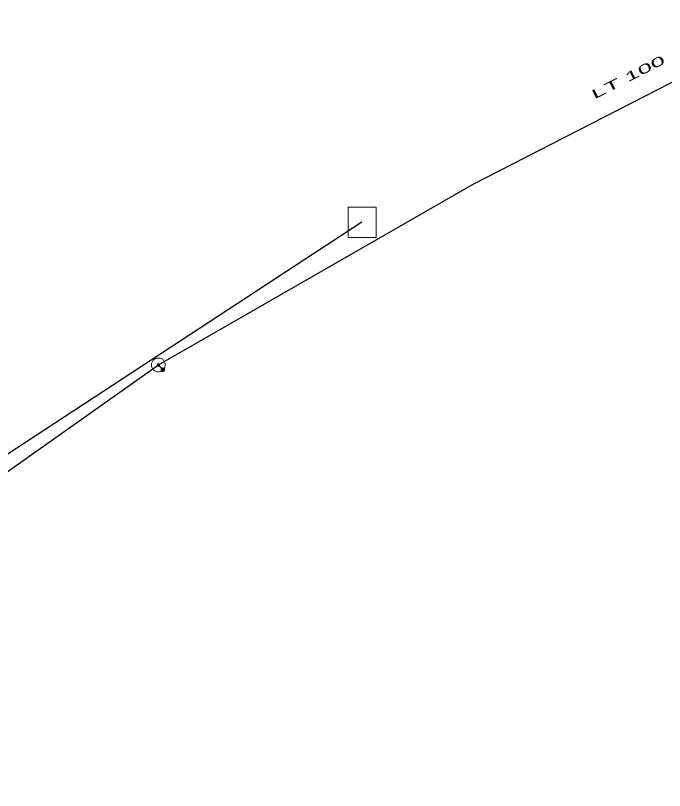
# Model space of a CAD drawing. Extents: x -688296 to -687852, y -973332 to -972816.
# Drawn here: x -687982.8 to -687935.8, y -973181.4 to -973125.3 of the extents above; entities that cross this region are included whole.
import ezdxf
from ezdxf.enums import TextEntityAlignment as Align

# ---------------------------------------------------------------- set-up
doc = ezdxf.new("R2010")
doc.units = 0
doc.header["$LTSCALE"] = 0.27
for name, color, linetype, lineweight in [('1', 7, 'Continuous', 25), ('14', 7, 'Continuous', 13), ('17', 7, 'Continuous', 25), ('22', 7, 'Continuous', 13), ('47', 7, 'Continuous', 13), ('9', 7, 'Continuous', 13)]:
    doc.layers.add(name, color=color, linetype=linetype, lineweight=lineweight)

msp = doc.modelspace()

# ---------------------------------------------------------------- linework, layer by layer
at = {"layer": '14', "lineweight": 25}
msp.add_line((-687957.712, -973140.243), (-688017.39, -973179.289), dxfattribs=at)
at = {"layer": '14'}
msp.add_line((-687972.436, -973150.573), (-687972.119, -973150.919), dxfattribs=at)
at = {"layer": '17'}
for points in [[(-687972.436, -973150.573), (-687949.647, -973137.493), (-687925.819, -973125.269)], [(-687987.568, -973219.849), (-688011, -973191.963), (-688018.429, -973183.079), (-687972.436, -973150.573)]]:
    msp.add_lwpolyline(points, dxfattribs=at)
at = {"layer": '22'}
msp.add_lwpolyline([(-687958.692, -973139.153), (-687956.659, -973139.153), (-687956.659, -973141.346), (-687958.692, -973141.346)], close=True, dxfattribs=at)
at = {"layer": '47'}
for points in [[(-687972.098, -973150.941), (-687972.061, -973150.904), (-687972.028, -973150.863), (-687972.001, -973150.819), (-687971.977, -973150.772), (-687971.959, -973150.723), (-687971.946, -973150.672), (-687971.939, -973150.62), (-687971.936, -973150.568), (-687971.939, -973150.516), (-687971.947, -973150.464), (-687971.961, -973150.413), (-687971.981, -973150.365), (-687972.005, -973150.319), (-687972.034, -973150.275), (-687972.067, -973150.235), (-687972.104, -973150.198), (-687972.145, -973150.165), (-687972.19, -973150.137), (-687972.236, -973150.114), (-687972.285, -973150.096), (-687972.336, -973150.083), (-687972.388, -973150.075), (-687972.441, -973150.073), (-687972.492, -973150.075), (-687972.544, -973150.084), (-687972.595, -973150.098), (-687972.644, -973150.117), (-687972.689, -973150.142), (-687972.733, -973150.171), (-687972.773, -973150.204), (-687972.81, -973150.241), (-687972.843, -973150.282), (-687972.871, -973150.326), (-687972.894, -973150.373), (-687972.912, -973150.422), (-687972.926, -973150.472), (-687972.934, -973150.525), (-687972.936, -973150.577), (-687972.933, -973150.629), (-687972.924, -973150.681), (-687972.91, -973150.732), (-687972.891, -973150.78), (-687972.866, -973150.826), (-687972.837, -973150.87), (-687972.804, -973150.91), (-687972.767, -973150.947), (-687972.726, -973150.98), (-687972.682, -973151.008), (-687972.635, -973151.031), (-687972.586, -973151.049), (-687972.536, -973151.063), (-687972.484, -973151.07), (-687972.432, -973151.072), (-687972.379, -973151.069), (-687972.327, -973151.061), (-687972.276, -973151.047), (-687972.229, -973151.027), (-687972.182, -973151.003), (-687972.138, -973150.974)], [(-687972.38, -973150.633), (-687972.373, -973150.627), (-687972.369, -973150.62), (-687972.364, -973150.613), (-687972.361, -973150.606), (-687972.357, -973150.597), (-687972.356, -973150.589), (-687972.354, -973150.58), (-687972.353, -973150.572), (-687972.354, -973150.563), (-687972.355, -973150.555), (-687972.358, -973150.546), (-687972.361, -973150.538), (-687972.365, -973150.531), (-687972.369, -973150.524), (-687972.375, -973150.517), (-687972.381, -973150.51), (-687972.388, -973150.506), (-687972.395, -973150.501), (-687972.402, -973150.498), (-687972.411, -973150.494), (-687972.419, -973150.493), (-687972.428, -973150.491), (-687972.436, -973150.49), (-687972.445, -973150.491), (-687972.453, -973150.492), (-687972.462, -973150.495), (-687972.47, -973150.498), (-687972.477, -973150.502), (-687972.484, -973150.506), (-687972.491, -973150.512), (-687972.498, -973150.518), (-687972.502, -973150.525), (-687972.507, -973150.532), (-687972.51, -973150.539), (-687972.514, -973150.548), (-687972.516, -973150.556), (-687972.517, -973150.565), (-687972.518, -973150.573), (-687972.517, -973150.582), (-687972.516, -973150.59), (-687972.513, -973150.599), (-687972.51, -973150.607), (-687972.506, -973150.614), (-687972.502, -973150.621), (-687972.496, -973150.628), (-687972.49, -973150.635), (-687972.483, -973150.639), (-687972.476, -973150.644), (-687972.469, -973150.647), (-687972.46, -973150.651), (-687972.452, -973150.653), (-687972.443, -973150.654), (-687972.435, -973150.655), (-687972.426, -973150.654), (-687972.418, -973150.653), (-687972.409, -973150.65), (-687972.401, -973150.647), (-687972.394, -973150.643), (-687972.387, -973150.639)]]:
    msp.add_lwpolyline(points, close=True, dxfattribs=at)
at = {"layer": '9'}
for points in [[(-687972.245, -973150.919), (-687972.245, -973150.932), (-687972.242, -973150.945), (-687972.24, -973150.958), (-687972.235, -973150.97), (-687972.228, -973150.982), (-687972.222, -973150.993), (-687972.213, -973151.003), (-687972.203, -973151.013), (-687972.193, -973151.021), (-687972.183, -973151.028), (-687972.171, -973151.034), (-687972.159, -973151.039), (-687972.146, -973151.042), (-687972.132, -973151.044), (-687972.12, -973151.046), (-687972.107, -973151.045), (-687972.093, -973151.043), (-687972.081, -973151.04), (-687972.068, -973151.035), (-687972.056, -973151.029), (-687972.046, -973151.022), (-687972.036, -973151.014), (-687972.026, -973151.004), (-687972.017, -973150.994), (-687972.011, -973150.983), (-687972.005, -973150.971), (-687972, -973150.959), (-687971.997, -973150.946), (-687971.995, -973150.933), (-687971.992, -973150.92), (-687971.994, -973150.907), (-687971.995, -973150.894), (-687971.999, -973150.881), (-687972.004, -973150.869), (-687972.009, -973150.857), (-687972.017, -973150.846), (-687972.024, -973150.836), (-687972.034, -973150.826), (-687972.044, -973150.818), (-687972.056, -973150.811), (-687972.068, -973150.805), (-687972.08, -973150.8), (-687972.093, -973150.797), (-687972.105, -973150.795), (-687972.119, -973150.794), (-687972.132, -973150.794), (-687972.144, -973150.796), (-687972.157, -973150.799), (-687972.169, -973150.804), (-687972.181, -973150.81), (-687972.193, -973150.817), (-687972.203, -973150.825), (-687972.213, -973150.835), (-687972.22, -973150.845), (-687972.228, -973150.856), (-687972.233, -973150.868), (-687972.239, -973150.88), (-687972.242, -973150.893), (-687972.244, -973150.906)], [(-687972.225, -973150.919), (-687972.225, -973150.93), (-687972.223, -973150.941), (-687972.22, -973150.952), (-687972.217, -973150.962), (-687972.212, -973150.972), (-687972.206, -973150.981), (-687972.198, -973150.99), (-687972.191, -973150.998), (-687972.181, -973151.005), (-687972.173, -973151.011), (-687972.163, -973151.016), (-687972.152, -973151.02), (-687972.142, -973151.023), (-687972.13, -973151.026), (-687972.12, -973151.026), (-687972.108, -973151.026), (-687972.098, -973151.024), (-687972.087, -973151.021), (-687972.076, -973151.017), (-687972.066, -973151.012), (-687972.058, -973151.006), (-687972.049, -973150.999), (-687972.041, -973150.991), (-687972.034, -973150.982), (-687972.027, -973150.973), (-687972.022, -973150.963), (-687972.019, -973150.953), (-687972.016, -973150.942), (-687972.014, -973150.931), (-687972.012, -973150.92), (-687972.012, -973150.909), (-687972.014, -973150.898), (-687972.017, -973150.887), (-687972.022, -973150.877), (-687972.027, -973150.867), (-687972.032, -973150.858), (-687972.039, -973150.849), (-687972.048, -973150.841), (-687972.056, -973150.834), (-687972.066, -973150.828), (-687972.076, -973150.823), (-687972.085, -973150.819), (-687972.097, -973150.816), (-687972.107, -973150.814), (-687972.119, -973150.814), (-687972.13, -973150.813), (-687972.141, -973150.815), (-687972.152, -973150.818), (-687972.161, -973150.822), (-687972.171, -973150.827), (-687972.181, -973150.833), (-687972.19, -973150.84), (-687972.198, -973150.848), (-687972.205, -973150.857), (-687972.21, -973150.866), (-687972.215, -973150.876), (-687972.22, -973150.886), (-687972.223, -973150.897), (-687972.225, -973150.908)], [(-687972.206, -973150.919), (-687972.206, -973150.928), (-687972.205, -973150.937), (-687972.201, -973150.946), (-687972.198, -973150.954), (-687972.195, -973150.962), (-687972.19, -973150.97), (-687972.183, -973150.977), (-687972.178, -973150.983), (-687972.171, -973150.989), (-687972.163, -973150.994), (-687972.154, -973150.998), (-687972.147, -973151.001), (-687972.137, -973151.004), (-687972.129, -973151.005), (-687972.12, -973151.007), (-687972.11, -973151.006), (-687972.102, -973151.005), (-687972.093, -973151.002), (-687972.085, -973150.999), (-687972.076, -973150.995), (-687972.068, -973150.99), (-687972.061, -973150.984), (-687972.056, -973150.978), (-687972.049, -973150.971), (-687972.044, -973150.963), (-687972.041, -973150.955), (-687972.038, -973150.947), (-687972.034, -973150.938), (-687972.034, -973150.929), (-687972.031, -973150.92), (-687972.032, -973150.911), (-687972.034, -973150.902), (-687972.036, -973150.893), (-687972.039, -973150.885), (-687972.044, -973150.877), (-687972.049, -973150.869), (-687972.054, -973150.862), (-687972.061, -973150.856), (-687972.068, -973150.85), (-687972.076, -973150.845), (-687972.083, -973150.841), (-687972.092, -973150.838), (-687972.1, -973150.835), (-687972.11, -973150.834), (-687972.119, -973150.833), (-687972.127, -973150.833), (-687972.137, -973150.834), (-687972.146, -973150.837), (-687972.154, -973150.84), (-687972.161, -973150.844), (-687972.169, -973150.849), (-687972.176, -973150.855), (-687972.183, -973150.861), (-687972.188, -973150.868), (-687972.193, -973150.876), (-687972.198, -973150.884), (-687972.201, -973150.892), (-687972.203, -973150.901), (-687972.205, -973150.91)], [(-687972.186, -973150.919), (-687972.186, -973150.926), (-687972.184, -973150.933), (-687972.183, -973150.94), (-687972.181, -973150.946), (-687972.178, -973150.952), (-687972.174, -973150.958), (-687972.169, -973150.964), (-687972.164, -973150.969), (-687972.159, -973150.973), (-687972.152, -973150.977), (-687972.147, -973150.98), (-687972.141, -973150.983), (-687972.134, -973150.984), (-687972.127, -973150.987), (-687972.12, -973150.987), (-687972.112, -973150.987), (-687972.105, -973150.985), (-687972.098, -973150.984), (-687972.093, -973150.981), (-687972.085, -973150.978), (-687972.081, -973150.974), (-687972.075, -973150.97), (-687972.07, -973150.965), (-687972.066, -973150.959), (-687972.061, -973150.953), (-687972.058, -973150.947), (-687972.056, -973150.941), (-687972.054, -973150.934), (-687972.053, -973150.927), (-687972.051, -973150.92), (-687972.051, -973150.913), (-687972.053, -973150.906), (-687972.054, -973150.899), (-687972.058, -973150.893), (-687972.061, -973150.886), (-687972.065, -973150.881), (-687972.068, -973150.875), (-687972.073, -973150.87), (-687972.08, -973150.866), (-687972.085, -973150.862), (-687972.092, -973150.859), (-687972.098, -973150.856), (-687972.105, -973150.854), (-687972.112, -973150.853), (-687972.119, -973150.853), (-687972.125, -973150.853), (-687972.132, -973150.853), (-687972.139, -973150.855), (-687972.146, -973150.858), (-687972.152, -973150.861), (-687972.157, -973150.865), (-687972.164, -973150.869), (-687972.169, -973150.874), (-687972.173, -973150.88), (-687972.176, -973150.885), (-687972.179, -973150.892), (-687972.183, -973150.898), (-687972.183, -973150.905), (-687972.186, -973150.912)], [(-687972.166, -973150.919), (-687972.166, -973150.924), (-687972.166, -973150.929), (-687972.164, -973150.934), (-687972.163, -973150.938), (-687972.161, -973150.943), (-687972.157, -973150.947), (-687972.154, -973150.95), (-687972.151, -973150.954), (-687972.147, -973150.957), (-687972.144, -973150.96), (-687972.139, -973150.962), (-687972.134, -973150.964), (-687972.13, -973150.965), (-687972.125, -973150.967), (-687972.12, -973150.967), (-687972.115, -973150.967), (-687972.11, -973150.966), (-687972.105, -973150.965), (-687972.1, -973150.963), (-687972.095, -973150.961), (-687972.092, -973150.958), (-687972.088, -973150.955), (-687972.085, -973150.951), (-687972.081, -973150.948), (-687972.078, -973150.944), (-687972.076, -973150.939), (-687972.075, -973150.935), (-687972.073, -973150.93), (-687972.073, -973150.925), (-687972.071, -973150.92), (-687972.071, -973150.915), (-687972.073, -973150.91), (-687972.073, -973150.905), (-687972.076, -973150.901), (-687972.078, -973150.896), (-687972.081, -973150.892), (-687972.083, -973150.888), (-687972.087, -973150.885), (-687972.09, -973150.882), (-687972.095, -973150.879), (-687972.1, -973150.877), (-687972.103, -973150.875), (-687972.108, -973150.874), (-687972.114, -973150.873), (-687972.119, -973150.873), (-687972.124, -973150.873), (-687972.129, -973150.874), (-687972.134, -973150.874), (-687972.137, -973150.876), (-687972.142, -973150.878), (-687972.147, -973150.881), (-687972.149, -973150.884), (-687972.154, -973150.887), (-687972.156, -973150.891), (-687972.159, -973150.895), (-687972.161, -973150.9), (-687972.164, -973150.904), (-687972.164, -973150.909), (-687972.166, -973150.914)], [(-687972.146, -973150.919), (-687972.146, -973150.922), (-687972.147, -973150.925), (-687972.146, -973150.927), (-687972.144, -973150.93), (-687972.144, -973150.933), (-687972.142, -973150.935), (-687972.139, -973150.937), (-687972.137, -973150.939), (-687972.136, -973150.941), (-687972.134, -973150.943), (-687972.13, -973150.945), (-687972.127, -973150.946), (-687972.125, -973150.946), (-687972.122, -973150.947), (-687972.12, -973150.947), (-687972.117, -973150.947), (-687972.114, -973150.947), (-687972.11, -973150.946), (-687972.108, -973150.945), (-687972.105, -973150.944), (-687972.103, -973150.942), (-687972.1, -973150.94), (-687972.098, -973150.938), (-687972.098, -973150.936), (-687972.095, -973150.934), (-687972.095, -973150.931), (-687972.093, -973150.928), (-687972.093, -973150.926), (-687972.092, -973150.923), (-687972.09, -973150.92), (-687972.092, -973150.917), (-687972.092, -973150.914), (-687972.093, -973150.911), (-687972.093, -973150.909), (-687972.095, -973150.906), (-687972.097, -973150.904), (-687972.098, -973150.901), (-687972.1, -973150.899), (-687972.103, -973150.898), (-687972.105, -973150.896), (-687972.107, -973150.895), (-687972.11, -973150.894), (-687972.112, -973150.893), (-687972.115, -973150.893), (-687972.119, -973150.892), (-687972.122, -973150.893), (-687972.125, -973150.892), (-687972.127, -973150.894), (-687972.13, -973150.894), (-687972.132, -973150.895), (-687972.134, -973150.897), (-687972.137, -973150.898), (-687972.139, -973150.9), (-687972.141, -973150.903), (-687972.142, -973150.905), (-687972.144, -973150.908), (-687972.144, -973150.91), (-687972.146, -973150.913), (-687972.146, -973150.916)], [(-687972.127, -973150.919), (-687972.127, -973150.921), (-687972.127, -973150.921), (-687972.125, -973150.921), (-687972.125, -973150.923), (-687972.127, -973150.924), (-687972.125, -973150.924), (-687972.125, -973150.924), (-687972.125, -973150.926), (-687972.125, -973150.926), (-687972.124, -973150.927), (-687972.122, -973150.927), (-687972.122, -973150.927), (-687972.122, -973150.928), (-687972.12, -973150.928), (-687972.12, -973150.928), (-687972.119, -973150.928), (-687972.117, -973150.928), (-687972.117, -973150.927), (-687972.117, -973150.927), (-687972.115, -973150.927), (-687972.115, -973150.926), (-687972.115, -973150.926), (-687972.114, -973150.925), (-687972.114, -973150.925), (-687972.112, -973150.924), (-687972.112, -973150.923), (-687972.11, -973150.922), (-687972.11, -973150.922), (-687972.11, -973150.921), (-687972.11, -973150.92), (-687972.11, -973150.919), (-687972.11, -973150.918), (-687972.11, -973150.918), (-687972.112, -973150.917), (-687972.112, -973150.916), (-687972.112, -973150.915), (-687972.112, -973150.915), (-687972.114, -973150.914), (-687972.114, -973150.914), (-687972.115, -973150.913), (-687972.115, -973150.913), (-687972.117, -973150.912), (-687972.117, -973150.912), (-687972.117, -973150.912), (-687972.119, -973150.912), (-687972.12, -973150.912), (-687972.12, -973150.912), (-687972.12, -973150.912), (-687972.122, -973150.913), (-687972.122, -973150.912), (-687972.124, -973150.914), (-687972.124, -973150.914), (-687972.125, -973150.914), (-687972.125, -973150.914), (-687972.125, -973150.916), (-687972.125, -973150.917), (-687972.125, -973150.918), (-687972.127, -973150.918), (-687972.127, -973150.919)]]:
    msp.add_lwpolyline(points, close=True, dxfattribs=at)

# ---------------------------------------------------------------- texts
at = {"layer": '1', "width": 2.1}
msp.add_text('LT 100', height=0.6667, rotation=27, dxfattribs=at).set_placement((-687938.2593, -973130.027), align=Align.CENTER)
msp.add_text('LT 100', height=0.6667, rotation=27, dxfattribs=at).set_placement((-687938.2593, -973130.027), align=Align.CENTER)
msp.add_text('LT 100', height=0.6667, rotation=27, dxfattribs=at).set_placement((-687938.2593, -973130.027), align=Align.CENTER)
msp.add_text('LT 100', height=0.6667, rotation=27, dxfattribs=at).set_placement((-687938.2593, -973130.027), align=Align.CENTER)
msp.add_text('LT 100', height=0.6667, rotation=27, dxfattribs=at).set_placement((-687938.2593, -973130.027), align=Align.CENTER)

doc.saveas('drawing.dxf')
